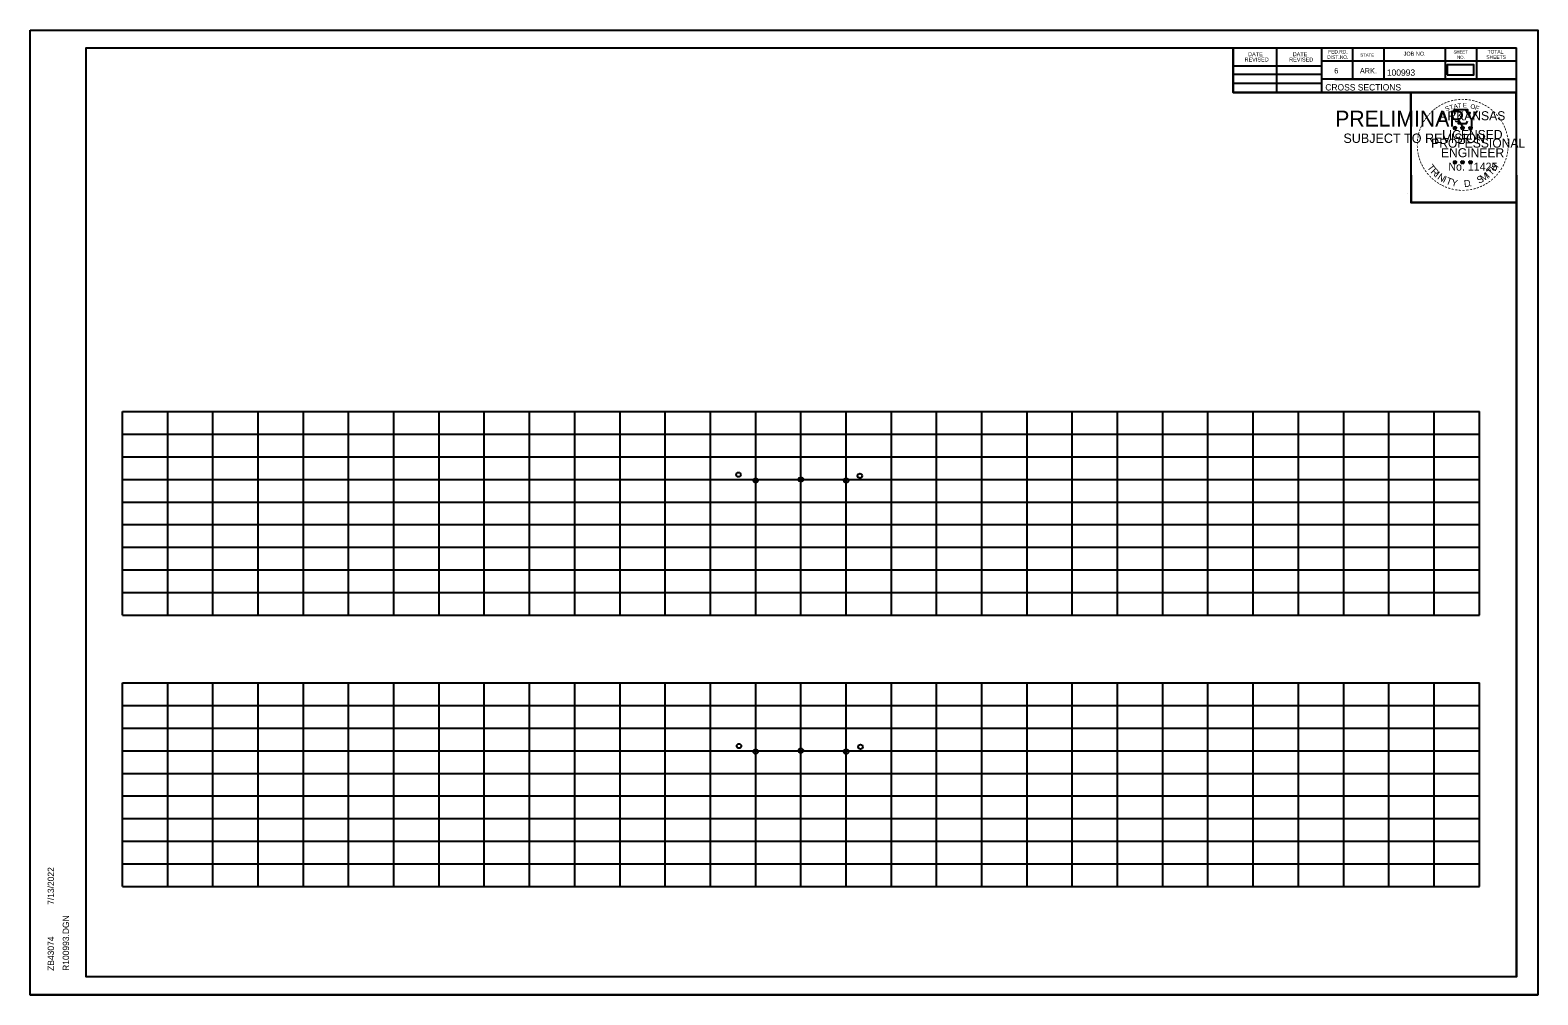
# Model space of a CAD drawing. Extents: x 4667 to 1632277, y -2100 to 724501.
# Drawn here: x 8926.7 to 9260, y -795.9 to -582.6 of the extents above; entities that cross this region are included whole.
import ezdxf

# ---------------------------------------------------------------- set-up
doc = ezdxf.new("R2010")
doc.units = 0
doc.layers.add('R_Grid', color=7, linetype='Continuous')
doc.layers.add('R_No Plot', color=7, linetype='Continuous')

msp = doc.modelspace()

# ---------------------------------------------------------------- linework, layer by layer
at = {"layer": 'R_Grid'}
for p, q in [((8947.12, -666.93), (9247.12, -666.93)), ((8947.12, -711.93), (8947.12, -666.93)), ((8957.12, -711.93), (8957.12, -666.93)), ((8967.12, -711.93), (8967.12, -666.93)), ((8977.12, -711.93), (8977.12, -666.93)), ((8987.12, -711.93), (8987.12, -666.93)), ((8997.12, -711.93), (8997.12, -666.93)), ((9007.12, -711.93), (9007.12, -666.93)), ((9017.12, -711.93), (9017.12, -666.93)), ((9027.12, -711.93), (9027.12, -666.93)), ((9037.12, -711.93), (9037.12, -666.93)), ((9047.12, -711.93), (9047.12, -666.93)), ((9057.12, -711.93), (9057.12, -666.93)), ((9067.12, -711.93), (9067.12, -666.93)), ((9077.12, -711.93), (9077.12, -666.93)), ((9087.12, -711.93), (9087.12, -666.93)), ((9097.12, -711.93), (9097.12, -666.93)), ((9107.12, -711.93), (9107.12, -666.93)), ((9117.12, -711.93), (9117.12, -666.93)), ((9127.12, -711.93), (9127.12, -666.93)), ((9137.12, -711.93), (9137.12, -666.93)), ((9147.12, -711.93), (9147.12, -666.93)), ((9157.12, -711.93), (9157.12, -666.93)), ((9167.12, -711.93), (9167.12, -666.93)), ((9177.12, -711.93), (9177.12, -666.93)), ((9187.12, -711.93), (9187.12, -666.93)), ((9197.12, -711.93), (9197.12, -666.93)), ((9207.12, -711.93), (9207.12, -666.93)), ((9217.12, -711.93), (9217.12, -666.93)), ((9227.12, -711.93), (9227.12, -666.93)), ((9237.12, -711.93), (9237.12, -666.93)), ((9247.12, -711.93), (9247.12, -666.93)), ((8947.12, -671.93), (9247.12, -671.93)), ((8947.12, -676.93), (9247.12, -676.93)), ((8947.12, -681.93), (9247.12, -681.93)), ((8947.12, -686.93), (9247.12, -686.93)), ((8947.12, -691.93), (9247.12, -691.93)), ((8947.12, -696.93), (9247.12, -696.93)), ((8947.12, -701.93), (9247.12, -701.93)), ((8947.12, -706.93), (9247.12, -706.93)), ((8947.12, -711.93), (9247.12, -711.93)), ((8947.12, -726.93), (9247.12, -726.93)), ((8947.12, -771.93), (8947.12, -726.93)), ((8957.12, -771.93), (8957.12, -726.93)), ((8967.12, -771.93), (8967.12, -726.93)), ((8977.12, -771.93), (8977.12, -726.93)), ((8987.12, -771.93), (8987.12, -726.93)), ((8997.12, -771.93), (8997.12, -726.93)), ((9007.12, -771.93), (9007.12, -726.93)), ((9017.12, -771.93), (9017.12, -726.93)), ((9027.12, -771.93), (9027.12, -726.93)), ((9037.12, -771.93), (9037.12, -726.93)), ((9047.12, -771.93), (9047.12, -726.93)), ((9057.12, -771.93), (9057.12, -726.93)), ((9067.12, -771.93), (9067.12, -726.93)), ((9077.12, -771.93), (9077.12, -726.93)), ((9087.12, -771.93), (9087.12, -726.93)), ((9097.12, -771.93), (9097.12, -726.93)), ((9107.12, -771.93), (9107.12, -726.93)), ((9117.12, -771.93), (9117.12, -726.93)), ((9127.12, -771.93), (9127.12, -726.93)), ((9137.12, -771.93), (9137.12, -726.93)), ((9147.12, -771.93), (9147.12, -726.93)), ((9157.12, -771.93), (9157.12, -726.93)), ((9167.12, -771.93), (9167.12, -726.93)), ((9177.12, -771.93), (9177.12, -726.93)), ((9187.12, -771.93), (9187.12, -726.93)), ((9197.12, -771.93), (9197.12, -726.93)), ((9207.12, -771.93), (9207.12, -726.93)), ((9217.12, -771.93), (9217.12, -726.93)), ((9227.12, -771.93), (9227.12, -726.93)), ((9237.12, -771.93), (9237.12, -726.93)), ((9247.12, -771.93), (9247.12, -726.93)), ((8947.12, -731.93), (9247.12, -731.93)), ((8947.12, -736.93), (9247.12, -736.93)), ((8947.12, -741.93), (9247.12, -741.93)), ((8947.12, -746.93), (9247.12, -746.93)), ((8947.12, -751.93), (9247.12, -751.93)), ((8947.12, -756.93), (9247.12, -756.93)), ((8947.12, -761.93), (9247.12, -761.93)), ((8947.12, -766.93), (9247.12, -766.93)), ((8947.12, -771.93), (9247.12, -771.93))]:
    msp.add_line(p, q, dxfattribs=at)
at = {"layer": 'R_No Plot'}
for p, q in [((8926.72, -582.58), (9260.05, -582.58)), ((8939.12, -586.47), (9255.3, -586.47)), ((8939.12, -791.93), (8939.12, -586.47)), ((9192.66, -596.35), (9192.66, -586.47)), ((9202.34, -596.35), (9202.34, -586.47)), ((9212.2, -586.47), (9212.2, -596.35)), ((9219.04, -586.47), (9219.04, -593.41)), ((9225.98, -586.47), (9225.98, -593.41)), ((9239.56, -586.47), (9239.56, -593.41)), ((9246.5, -586.47), (9246.5, -593.41)), ((9255.3, -791.93), (9255.3, -586.47)), ((9091.64, -586.73), (9091.64, -586.73)), ((9091.64, -586.73), (9091.64, -586.73)), ((9255.3, -589.41), (9212.2, -589.41)), ((9255.3, -589.39), (9255.3, -589.39)), ((9192.66, -590.49), (9212.2, -590.49)), ((9192.66, -592.35), (9212.2, -592.35)), ((9192.66, -594.29), (9212.2, -594.29)), ((9255.3, -596.35), (9192.66, -596.35)), ((9255.3, -593.41), (9212.2, -593.41)), ((9215.16, -593.41), (9255.3, -593.41)), ((9241.38, -604.1), (9241.73, -604.21)), ((9241.38, -604.1), (9241.63, -604.14)), ((9241.38, -604.1), (9241.62, -604.22)), ((9241.51, -604.51), (9241.73, -604.21)), ((9241.51, -604.51), (9241.64, -604.26)), ((9241.51, -604.51), (9241.73, -604.29)), ((9241.73, -603.84), (9241.69, -604.1)), ((9241.73, -604.21), (9241.73, -603.84)), ((9241.73, -603.84), (9241.78, -604.09)), ((9242.08, -604.1), (9241.73, -604.21)), ((9241.94, -604.51), (9241.73, -604.21)), ((9241.94, -604.51), (9241.73, -604.29)), ((9242.08, -604.1), (9241.79, -604.15)), ((9241.94, -604.51), (9241.81, -604.22)), ((9242.08, -604.1), (9241.87, -604.2)), ((9243.05, -604.1), (9243.4, -604.21)), ((9243.05, -604.1), (9243.3, -604.14)), ((9243.05, -604.1), (9243.29, -604.22)), ((9243.18, -604.51), (9243.4, -604.21)), ((9243.18, -604.51), (9243.31, -604.26)), ((9243.18, -604.51), (9243.4, -604.29)), ((9243.4, -603.84), (9243.36, -604.1)), ((9243.4, -604.21), (9243.4, -603.84)), ((9243.4, -603.84), (9243.45, -604.09)), ((9243.75, -604.1), (9243.4, -604.21)), ((9243.61, -604.51), (9243.4, -604.21)), ((9243.61, -604.51), (9243.4, -604.29)), ((9243.75, -604.1), (9243.46, -604.15)), ((9243.61, -604.51), (9243.48, -604.22)), ((9243.75, -604.1), (9243.54, -604.2)), ((9244.82, -604.11), (9245.16, -604.22)), ((9244.82, -604.11), (9245.07, -604.16)), ((9244.82, -604.11), (9245.05, -604.23)), ((9244.95, -604.52), (9245.16, -604.22)), ((9244.95, -604.52), (9245.07, -604.27)), ((9244.95, -604.52), (9245.16, -604.3)), ((9245.16, -603.86), (9245.12, -604.11)), ((9245.16, -604.22), (9245.16, -603.86)), ((9245.16, -603.86), (9245.21, -604.11)), ((9245.51, -604.11), (9245.16, -604.22)), ((9245.38, -604.52), (9245.16, -604.22)), ((9245.38, -604.52), (9245.16, -604.3)), ((9245.51, -604.11), (9245.23, -604.16)), ((9245.38, -604.52), (9245.24, -604.23)), ((9245.51, -604.11), (9245.31, -604.21)), ((9241.38, -611.67), (9241.73, -611.78)), ((9241.38, -611.67), (9241.63, -611.72)), ((9241.38, -611.67), (9241.61, -611.79)), ((9241.51, -612.08), (9241.73, -611.78)), ((9241.51, -612.08), (9241.64, -611.84)), ((9241.51, -612.08), (9241.72, -611.86)), ((9241.73, -611.42), (9241.69, -611.67)), ((9241.94, -612.08), (9241.72, -611.87)), ((9241.73, -611.78), (9241.73, -611.42)), ((9241.73, -611.42), (9241.78, -611.67)), ((9242.07, -611.67), (9241.73, -611.78)), ((9241.94, -612.08), (9241.73, -611.78)), ((9242.07, -611.67), (9241.79, -611.72)), ((9241.94, -612.08), (9241.8, -611.79)), ((9242.07, -611.67), (9241.87, -611.77)), ((9243.05, -611.67), (9243.4, -611.78)), ((9243.05, -611.67), (9243.3, -611.72)), ((9243.05, -611.67), (9243.28, -611.79)), ((9243.18, -612.08), (9243.4, -611.78)), ((9243.18, -612.08), (9243.31, -611.84)), ((9243.18, -612.08), (9243.39, -611.86)), ((9243.4, -611.42), (9243.35, -611.67)), ((9243.61, -612.08), (9243.39, -611.87)), ((9243.4, -611.78), (9243.4, -611.42)), ((9243.4, -611.42), (9243.44, -611.67)), ((9243.74, -611.67), (9243.4, -611.78)), ((9243.61, -612.08), (9243.4, -611.78)), ((9243.74, -611.67), (9243.46, -611.72)), ((9243.61, -612.08), (9243.47, -611.79)), ((9243.74, -611.67), (9243.54, -611.77)), ((9244.81, -611.68), (9245.16, -611.79)), ((9244.81, -611.68), (9245.07, -611.73)), ((9244.81, -611.68), (9245.05, -611.8)), ((9244.95, -612.09), (9245.16, -611.79)), ((9244.95, -612.09), (9245.07, -611.85)), ((9244.95, -612.09), (9245.16, -611.87)), ((9245.16, -611.43), (9245.12, -611.68)), ((9245.16, -611.79), (9245.16, -611.43)), ((9245.16, -611.43), (9245.21, -611.68)), ((9245.51, -611.68), (9245.16, -611.79)), ((9245.38, -612.09), (9245.16, -611.79)), ((9245.38, -612.09), (9245.16, -611.88)), ((9245.51, -611.68), (9245.22, -611.73)), ((9245.38, -612.09), (9245.24, -611.8)), ((9245.51, -611.68), (9245.31, -611.78)), ((9231.33, -618.81), (9231.33, -618.81)), ((8939.12, -791.93), (8939.12, -791.93)), ((9255.3, -791.93), (8939.12, -791.93)), ((8926.72, -795.91), (9260.05, -795.91))]:
    msp.add_line(p, q, dxfattribs=at)
for points in [[(8926.71, -582.58), (9260.05, -582.58), (9260.05, -795.92), (8926.71, -795.92)], [(9173.04, -586.47), (9192.66, -586.47), (9192.66, -596.35), (9208.77, -596.35), (9231.97, -596.35), (9231.97, -620.69), (9255.3, -620.69), (9255.3, -791.93), (8939.12, -791.93), (8939.12, -586.47)], [(9240.03, -592.47), (9245.86, -592.47), (9245.86, -590.28), (9240.03, -590.28)], [(9231.97, -596.35), (9255.18, -596.35), (9255.3, -620.69), (9232.09, -620.69)]]:
    msp.add_lwpolyline(points, close=True, dxfattribs=at)
for points in [[(9241.42, -600.22), (9241.69, -601.05)], [(9244.93, -601.14), (9245.08, -600.86), (9244.39, -600.88), (9244.54, -600.22), (9241.42, -600.22)], [(9241.91, -602.64), (9241.91, -602.73), (9242.48, -602.75), (9242.42, -603.22), (9244.29, -603.22), (9244.49, -602.69)], [(9241.73, -603.84), (9241.94, -604.51), (9241.38, -604.1), (9242.08, -604.1), (9241.51, -604.51), (9241.73, -603.84)], [(9243.4, -603.84), (9243.61, -604.51), (9243.05, -604.1), (9243.75, -604.1), (9243.18, -604.51), (9243.4, -603.84)], [(9245.16, -603.86), (9245.38, -604.52), (9244.82, -604.11), (9245.51, -604.11), (9244.95, -604.52), (9245.16, -603.86)], [(9241.73, -611.42), (9241.94, -612.08), (9241.38, -611.67), (9242.07, -611.67), (9241.51, -612.08), (9241.73, -611.42)], [(9243.4, -611.42), (9243.61, -612.08), (9243.05, -611.67), (9243.74, -611.67), (9243.18, -612.08), (9243.4, -611.42)], [(9245.16, -611.43), (9245.38, -612.09), (9244.81, -611.68), (9245.51, -611.68), (9244.95, -612.09), (9245.16, -611.43)]]:
    msp.add_lwpolyline(points, dxfattribs=at)
for centre, radius in [((9241.73, -604.21), 0.172), ((9241.73, -604.21), 0.145), ((9241.73, -604.21), 0.116), ((9241.73, -604.21), 0.0991), ((9241.73, -604.21), 0.0747), ((9241.73, -604.21), 0.0495), ((9241.73, -604.21), 0.0296), ((9243.4, -604.21), 0.172), ((9243.4, -604.21), 0.145), ((9243.4, -604.21), 0.116), ((9243.4, -604.21), 0.0991), ((9243.4, -604.21), 0.0747), ((9243.4, -604.21), 0.0495), ((9243.4, -604.21), 0.0296), ((9245.16, -604.22), 0.172), ((9245.16, -604.22), 0.145), ((9245.16, -604.22), 0.116), ((9245.16, -604.22), 0.0991), ((9245.16, -604.22), 0.0747), ((9245.16, -604.22), 0.0495), ((9245.16, -604.22), 0.0296), ((9241.73, -611.78), 0.172), ((9241.73, -611.78), 0.145), ((9241.73, -611.78), 0.116), ((9241.73, -611.78), 0.0991), ((9241.73, -611.78), 0.0747), ((9241.73, -611.78), 0.0495), ((9241.73, -611.78), 0.0296), ((9243.39, -611.78), 0.172), ((9243.39, -611.78), 0.145), ((9243.39, -611.78), 0.116), ((9243.39, -611.78), 0.0991), ((9243.39, -611.78), 0.0747), ((9243.39, -611.78), 0.0495), ((9243.39, -611.78), 0.0296), ((9245.16, -611.79), 0.172), ((9245.16, -611.79), 0.145), ((9245.16, -611.79), 0.116), ((9245.16, -611.79), 0.0991), ((9245.16, -611.79), 0.0747), ((9245.16, -611.79), 0.0495), ((9245.16, -611.79), 0.0296), ((9083.31, -680.89), 0.5), ((9087.12, -682.16), 0.5), ((9097.12, -681.96), 0.5), ((9107.12, -682.16), 0.5), ((9110.16, -681.14), 0.5), ((9083.44, -740.9), 0.5), ((9087.12, -742.12), 0.5), ((9097.12, -741.92), 0.5), ((9107.12, -742.12), 0.5), ((9110.3, -741.06), 0.5)]:
    msp.add_circle(centre, radius, dxfattribs=at)

# ---------------------------------------------------------------- texts
for s, height, rotation, p in [('REVISED', 0.879, 360, (9195.21, -589.52)), ('DATE', 0.879, 360, (9195.99, -588.34)), ('REVISED', 0.879, 360, (9205.07, -589.52)), ('DATE', 0.879, 360, (9205.85, -588.34)), ('DIST.NO.', 0.782, 360, (9213.48, -588.93)), ('FED.RD.', 0.782, 360, (9213.68, -587.75)), ('STATE', 0.684, 360, (9220.8, -588.43)), ('JOB NO.', 0.879, 360, (9230.38, -588.23)), ('SHEET', 0.684, 360, (9241.42, -587.75)), ('NO.', 0.684, 360, (9242.2, -588.93)), ('SHEETS', 0.782, 360, (9248.66, -588.93)), ('TOTAL', 0.782, 360, (9248.94, -587.75)), ('6', 1.17, 360, (9215.04, -592.15)), ('ARK.', 1.172, 360, (9220.7, -592.15)), ('100993', 1.4, 360, (9226.67, -592.67)), ('CROSS SECTIONS', 1.4, 360, (9213.06, -595.92)), ('-', 1.6, 38.9507, (9237.25, -600.82)), ('-', 1.6, 36.2317, (9237.73, -600.44)), ('-', 1.6, 34.0636, (9238.31, -600.05)), ('-', 1.6, 28.7918, (9238.9, -599.68)), ('-', 1.6, 24.3072, (9239.54, -599.36)), ('S', 1, 21.594, (9239.78, -600.54)), ('-', 1.6, 19.1761, (9240.17, -599.09)), ('T', 1, 16.4036, (9240.69, -600.21)), ('-', 1.6, 13.6301, (9240.92, -598.85)), ('A', 1, 11.2132, (9241.52, -599.96)), ('-', 1.6, 10.2193, (9241.6, -598.69)), ('T', 1, 6.0228, (9242.37, -599.79)), ('-', 1.6, 5.8968, (9242.33, -598.58)), ('-', 1.6, 0.1862, (9243.1, -598.51)), ('E', 1, 0.8323, (9243.47, -599.68)), ('-', 1.6, 357.743, (9243.82, -598.52)), ('-', 1.6, 352.1617, (9244.57, -598.58)), ('O', 1, 350.4515, (9245.08, -599.89)), ('-', 1.6, 347.2049, (9245.29, -598.69)), ('F', 1, 340.0707, (9246.03, -600.12)), ('-', 1.6, 342.3362, (9245.92, -598.85)), ('-', 1.6, 337.8551, (9246.66, -599.07)), ('-', 1.6, 334.1211, (9247.29, -599.34)), ('-', 1.6, 329.6409, (9247.87, -599.62)), ('-', 1.6, 325.8627, (9248.51, -599.98)), ('-', 1.6, 320.5297, (9249.12, -600.41)), ('PRELIMINARY', 3.5, 360, (9215.25, -603.89)), ('DWB', 0.01, 360, (9215.99, -602.04)), ('-', 1.6, 62.8713, (9234.92, -603.91)), ('-', 1.6, 58.0706, (9235.23, -603.3)), ('-', 1.6, 54.2325, (9235.56, -602.77)), ('-', 1.6, 50.6142, (9235.97, -602.2)), ('-', 1.6, 48.423, (9236.37, -601.72)), ('-', 1.6, 42.9622, (9236.82, -601.24)), ('ARKANSAS', 2, 360, (9238.28, -602.51)), ('-', 1.6, 315.5786, (9249.72, -600.9)), ('-', 1.6, 309.8797, (9250.29, -601.45)), ('-', 1.6, 306.6522, (9250.81, -602.05)), ('-', 1.4, 303.6753, (9251.3, -602.62)), ('-', 1.6, 299.6684, (9251.62, -603.23)), ('SUBJECT TO REVISION', 2.0751, 360, (9217.06, -607.52)), ('-', 1.6, 85.1863, (9234.03, -607.27)), ('-', 1.6, 81.2013, (9234.11, -606.58)), ('-', 1.6, 75.461, (9234.24, -605.87)), ('-', 1.6, 72.3945, (9234.44, -605.15)), ('-', 1.6, 67.7743, (9234.66, -604.52)), ('PROFESSIONAL', 2, 360, (9236.45, -608.56)), ('LICENSED', 2, 360, (9238.87, -606.66)), ('DWB', 0.01, 360, (9241.72, -604.21)), ('DWB', 0.01, 360, (9243.39, -604.21)), ('DWB', 0.01, 360, (9245.15, -604.23)), ('-', 1.6, 294.6628, (9251.94, -603.84)), ('-', 1.6, 290.5728, (9252.2, -604.41)), ('-', 1.6, 285.1233, (9252.43, -604.99)), ('-', 1.6, 280.5493, (9252.63, -605.74)), ('-', 1.6, 276.5962, (9252.79, -606.5)), ('-', 1.6, 94.1959, (9234.04, -608.7)), ('-', 1.6, 89.0622, (9234.01, -607.97)), ('-', 1.6, 98.9479, (9234.12, -609.36)), ('-', 1.6, 101.7149, (9234.25, -610.1)), ('ENGINEER', 2, 360, (9238.64, -610.69)), ('-', 1.6, 260.9953, (9252.8, -609.18)), ('-', 1.6, 263.5172, (9252.87, -608.52)), ('-', 1.6, 274.3301, (9252.85, -607.23)), ('-', 1.6, 269.9407, (9252.89, -607.86)), ('-', 1.6, 105.4578, (9234.41, -610.69)), ('-', 1.6, 109.0874, (9234.63, -611.32)), ('-', 1.6, 114.0643, (9234.88, -611.92)), ('-', 1.6, 115.7289, (9235.19, -612.54)), ('-', 1.6, 120.4471, (9235.54, -613.12)), ('T', 1.54, 306.0406, (9235.49, -612.94)), ('R', 1.54, 314.005, (9236.25, -613.99)), ('No. 11425', 1.757, 360, (9240.26, -613.64)), ('DWB', 0.01, 360, (9241.71, -611.79)), ('DWB', 0.01, 360, (9243.38, -611.79)), ('DWB', 0.01, 360, (9245.15, -611.8)), ('T', 1.54, 46.6444, (9249.72, -614.85)), ('H', 1.54, 54.6088, (9250.61, -613.91)), ('-', 1.6, 239.0712, (9251.63, -612.63)), ('-', 1.6, 244.6197, (9252.02, -611.88)), ('-', 1.6, 247.8887, (9252.28, -611.25)), ('-', 1.6, 252.8681, (9252.51, -610.58)), ('-', 1.6, 255.7626, (9252.69, -609.86)), ('-', 1.6, 125.8934, (9235.95, -613.68)), ('-', 1.6, 130.7181, (9236.41, -614.24)), ('-', 1.6, 134.2238, (9236.93, -614.78)), ('-', 1.6, 138.9338, (9237.45, -615.24)), ('-', 1.6, 144.6463, (9238.01, -615.65)), ('I', 1.54, 321.9694, (9237.15, -614.92)), ('-', 1.6, 148.0898, (9238.57, -616.02)), ('N', 1.54, 326.5002, (9237.72, -615.4)), ('-', 1.6, 151.5704, (9239.15, -616.35)), ('I', 1.54, 335.3603, (9238.92, -616.18)), ('T', 1.54, 339.8912, (9239.59, -616.51)), ('Y', 1.54, 347.8556, (9240.8, -616.95)), ('D', 1.54, 6.3969, (9243.79, -617.31)), ('S', 1.54, 26.9312, (9247.03, -616.58)), ('M', 1.54, 32.6563, (9247.87, -616.18)), ('-', 1.6, 207.3568, (9248.15, -616.13)), ('I', 1.54, 42.1136, (9249.15, -615.33)), ('-', 1.6, 212.2491, (9248.71, -615.78)), ('-', 1.6, 215.7363, (9249.25, -615.39)), ('-', 1.6, 221.0851, (9249.79, -614.92)), ('-', 1.6, 225.7653, (9250.32, -614.41)), ('-', 1.6, 231.2538, (9250.8, -613.85)), ('-', 1.6, 233.8452, (9251.23, -613.28)), ('-', 1.6, 154.6002, (9239.67, -616.59)), ('-', 1.6, 158.5612, (9240.29, -616.85)), ('-', 1.6, 162.7983, (9240.98, -617.06)), ('-', 1.6, 167.5555, (9241.7, -617.22)), ('-', 1.6, 173.1155, (9242.47, -617.33)), ('-', 1.6, 176.5183, (9243.22, -617.39)), ('-', 1.6, 181.5918, (9243.96, -617.37)), ('-', 1.6, 185.8167, (9244.77, -617.29)), ('-', 1.6, 191.2858, (9245.5, -617.16)), ('.', 1.54, 13.7642, (9244.98, -617.19)), ('-', 1.6, 195.4743, (9246.23, -616.96)), ('-', 1.6, 200.7184, (9246.91, -616.72)), ('-', 1.6, 204.2516, (9247.53, -616.45)), ('7/13/2022', 1.4, 90, (8931.98, -776.01)), ('R100993.DGN', 1.4, 90, (8935.31, -790.61)), ('ZB43074', 1.4, 90, (8931.98, -790.61))]:
    msp.add_text(s, height=height, rotation=rotation, dxfattribs=at).set_placement(p)

doc.saveas('drawing.dxf')
